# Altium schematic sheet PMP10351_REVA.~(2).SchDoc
size 431 x 279 mm; Date: Not shown in title block; ApprovedBy: Not shown in title block; CheckedBy: Not shown in title block; Author: Not shown in title block; CompanyName: Not shown in title block; Engineer: Not shown in title block; Organization: Not shown in title block; Address1: Not shown in title block; Address2: Not shown in title block; Address3: Not shown in title block; Address4: Not shown in title block; DocumentNumber: 1; Revision: Use project parameter SCH_Rev; SheetNumber: 1; SheetTotal: 1; PageSetup: Record=PageOptions|CenterHorizontal=True|CenterVertical=True|PrintScale=1.00|XCorrection=1.00|YCorrection=1.00|PrintKind=0|BorderSize=5000000|LeftOffset=0|BottomOffset=0|Orientation=2|PaperLength=1000|PaperWidth=1000|Scale=100|PaperSource=15|PrintQuality=600|MediaType=1|DitherType=10|PaperKind=Letter|PrintScaleMode=1
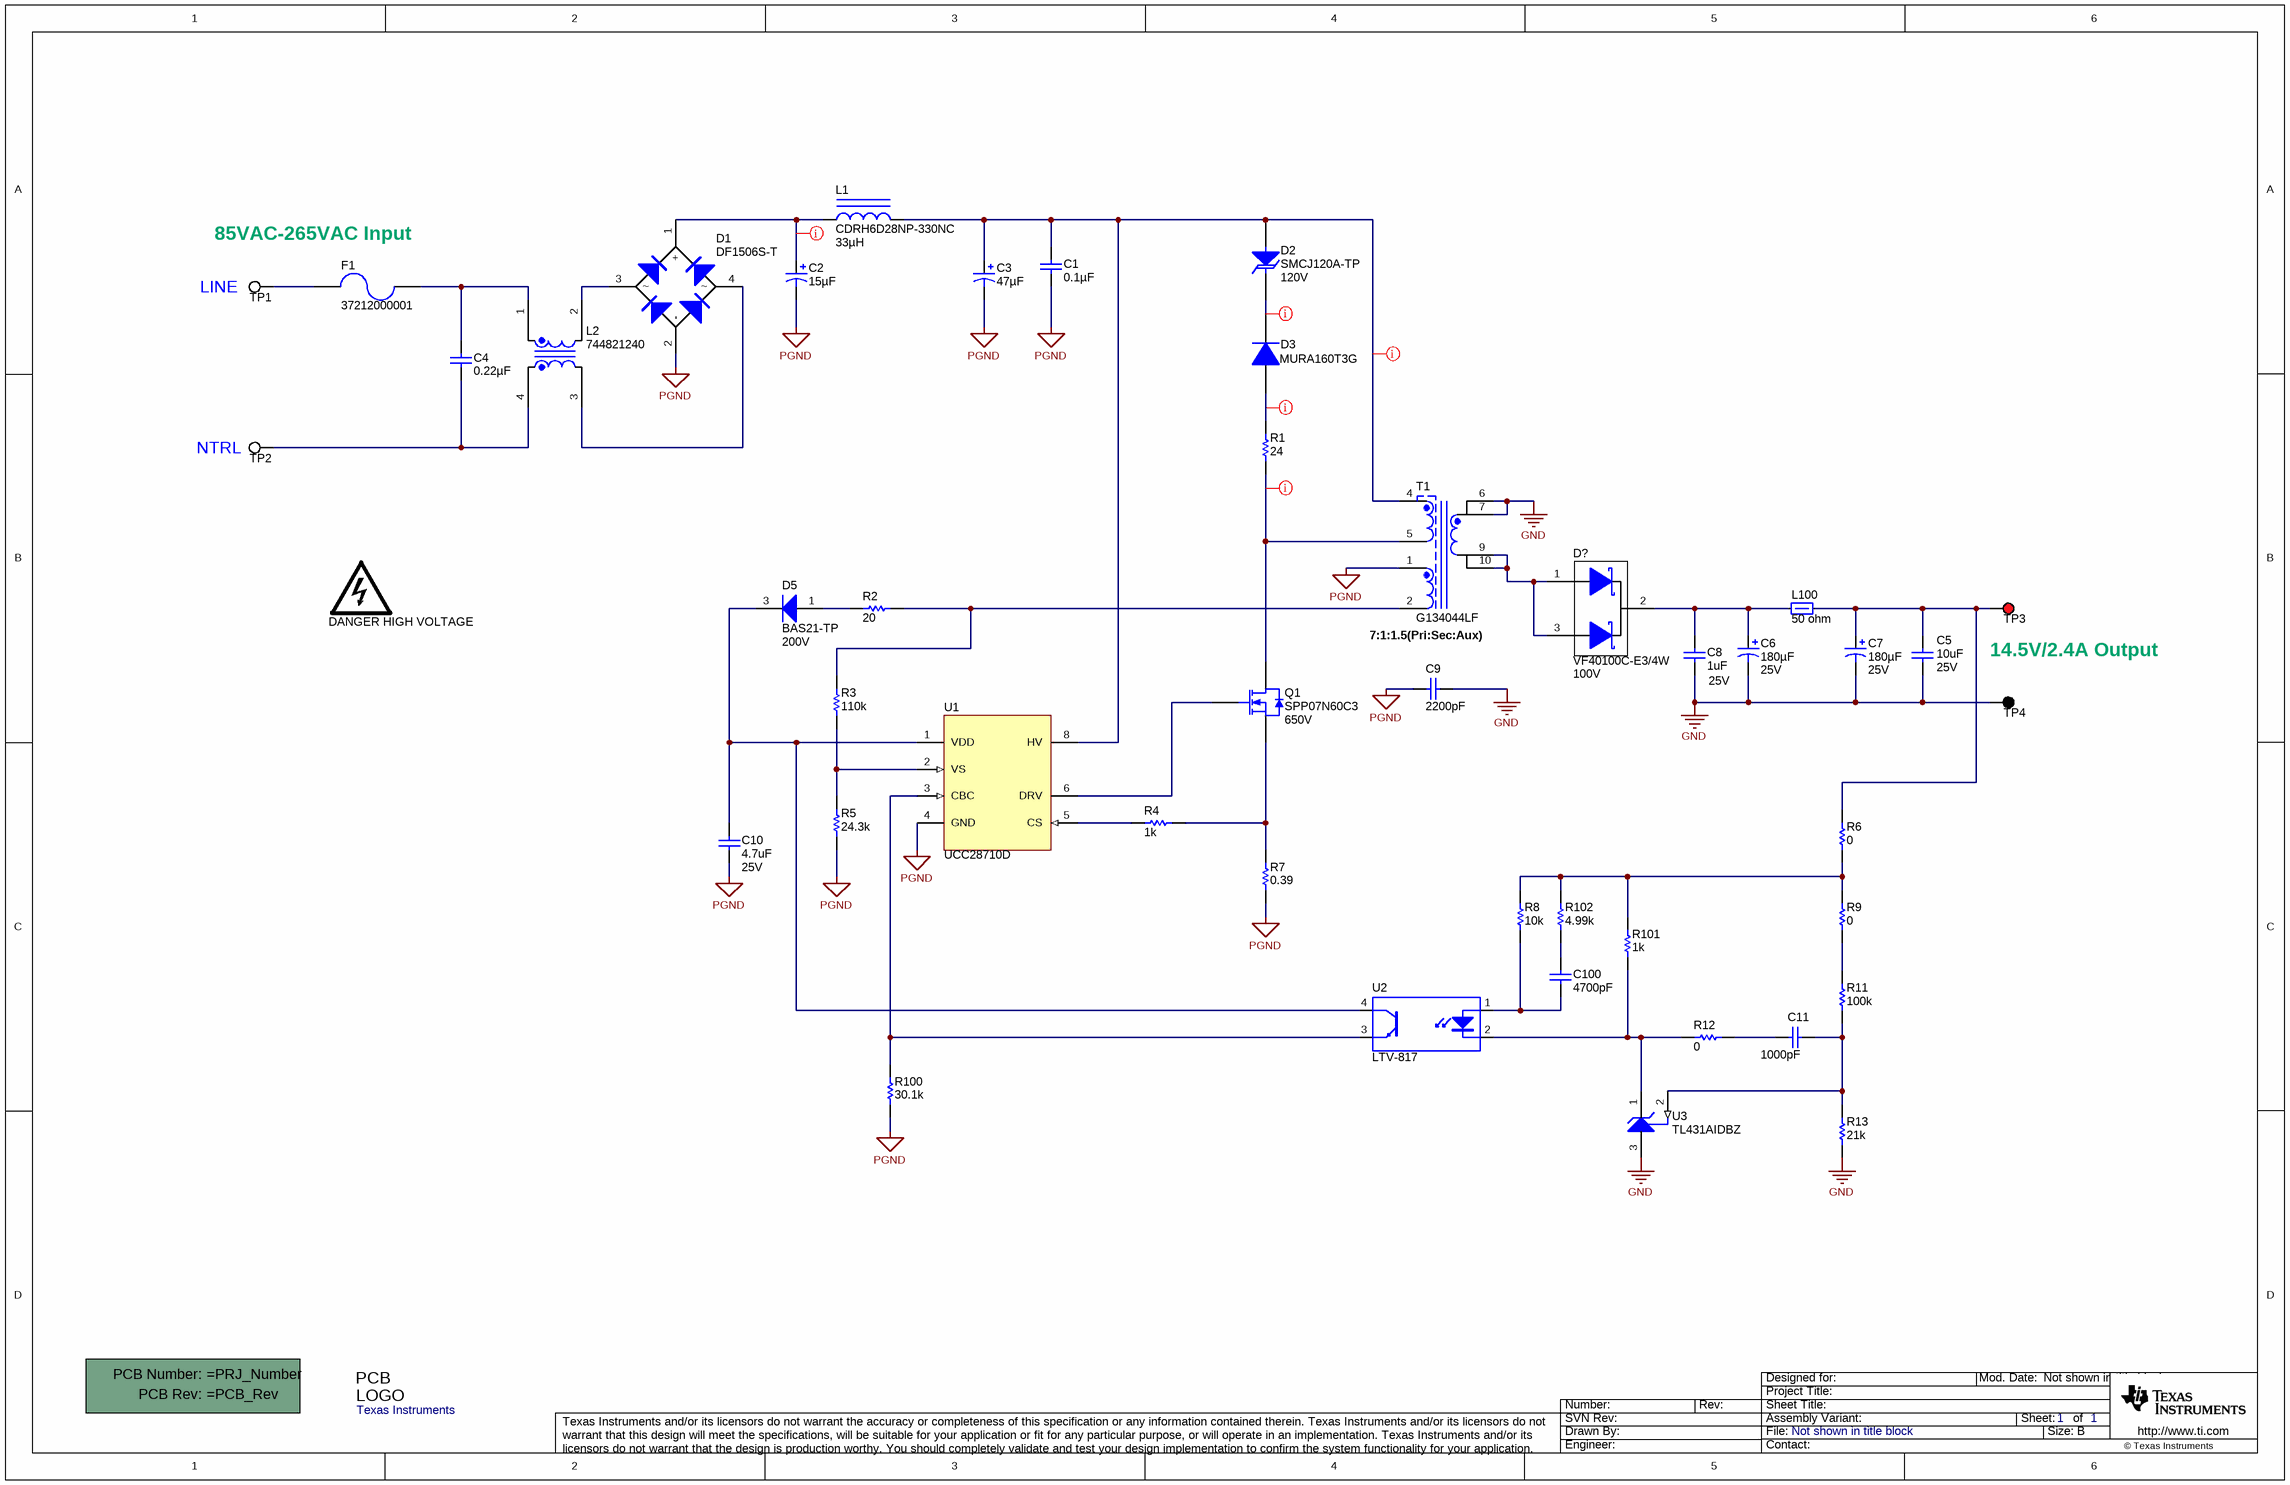
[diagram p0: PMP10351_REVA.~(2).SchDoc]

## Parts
(Parts that share a designator on the sheet are numbered #1, #2 ... from top to bottom, then left to right.)
!PCB  Printed Circuit Board  (value not drawn)  (mechanical)
C1  ValueDisplayed: 0.1µF  [1808_L]  (hidden comment: VJ1808Y104KXPAT5Z)
C2  ValueDisplayed: 15µF  [CAPPR5-12.5X20]  (hidden comment: EEUED2G150)
C3  ValueDisplayed: 47µF  [CAPPR7.5-18X20]  (hidden comment: EEUED2G470S)
C4  ValueDisplayed: 0.22µF  [B32922_12.5mm]  (hidden comment: B32922C3224M)
C5  value 10uF  Value2: 25V  [1206L]  (hidden comment: STD)
C6  ValueDisplayed: 180µF  Value2: 25V  [CAPPRD350W60D800H1150]  (hidden comment: 25SEPF180M)
C7  ValueDisplayed: 180µF  Value2: 25V  [CAPPRD350W60D800H1150]  (hidden comment: 25SEPF180M)
C8  value 1uF  Value2: 25V  [0805L]  (hidden comment: STD)
C9  ValueDisplayed: 2200pF  [CAPRD500W60D800H850]  (hidden comment: DE2E3KY222MA2BM01)
C10  value 4.7uF  Value2: 25V  [0805L]  (hidden comment: STD)
C11  value 1000pF  [0603L]  (hidden comment: STD)
C100  value 4700pF  [0603L]  (hidden comment: STD)
D1  DF1506S-T  [DF-S]
D2  SMCJ120A-TP  value 120V  [SMC]
D3  MURA160T3G  [SMA]
D5  BAS21-TP  value 200V  [SOT-23L]
D?  VF40100C-E3/4W  value 100V  [TO-220AB]
F1  37212000001  [FUSE_372]
L1  CDRH6D28NP-330NC  ValueDisplayed: 33µH  [CDRH6D28]
L2  744821240  [WE-CMB_XS]
L100  value 50 ohm  [1206L]  (hidden comment: HI1206T500R-10)
LOGO1#1  DANGER HIGH VOLTAGE  [IEC_HighVoltage_Small]  (no BOM)
Logo1#2  Texas Instruments  [TI_Stacked_SolderMask_Small]  (no BOM)
Q1  SPP07N60C3  value 650V  [TO-220AB]
R1  value 24  [2512L]  (hidden comment: STD)
R2  value 20  [0603L]  (hidden comment: STD)
R3  value 110k  [0603L]  (hidden comment: STD)
R4  value 1k  [0603L]  (hidden comment: STD)
R5  value 24.3k  [0603L]  (hidden comment: STD)
R6  value 0  [0603L]  (hidden comment: STD)
R7  value 0.39  [1210L]  (hidden comment: STD)
R8  value 10k  [0603L]  (hidden comment: STD)
R9  value 0  [0603L]  (hidden comment: STD)
R11  value 100k  [0603L]  (hidden comment: STD)
R12  value 0  [0603L]  (hidden comment: STD)
R13  value 21k  [0603L]  (hidden comment: STD)
R100  value 30.1k  [0603L]  (hidden comment: STD)
R101  value 1k  [0603L]  (hidden comment: STD)
R102  value 4.99k  [0603L]  (hidden comment: STD)
T1  G134044LF  [GCI_G134044LF]
TP1  5012  [Keystone5012]  (value not drawn)
TP2  5012  [Keystone5012]  (value not drawn)
TP3  5010  [Keystone5010]  (value not drawn)
TP4  5011  [Keystone5011]  (value not drawn)
U1  UCC28710D  [D0007A_L]
U2  LTV-817  [DIP762W60P254L460H350Q4B]
U3  TL431AIDBZ  [DBZ0003A_L]

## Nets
GND: C5.2 C6.2(-) C7.2(-) C8.2 C9.1 R13.1 T1.6 T1.7 TP4.1 U3.3(ANODE)
PGND: C1.2 C2.2(-) C3.2(-) C9.2 C10.2 D1.2(-) R5.1 R7.1 R100.1 T1.1 U1.4(GND)
NetC1_1: C1.1 C3.1(+) D2.2(A) L1.2 T1.4 U1.8(HV)
NetC2_1: C2.1(+) D1.1(+) L1.1
NetC4_1: C4.1 F1.1 L2.1
NetC4_2: C4.2 L2.4 TP2.1
NetC5_1: C5.1 C7.1(+) L100.2 R6.2 TP3.1
NetC6_1: C6.1(+) C8.1 D?.2(K) L100.1
NetC10_1: C10.1 D5.3(K) U1.1(VDD) U2.4(C)
NetC11_1: C11.1 R11.1 R13.2 U3.2(REF)
NetC11_2: C11.2 R12.1
NetC100_1: C100.1 R102.2
NetC100_2: C100.2 R8.1 U2.1(A)
NetD1_3: D1.3 L2.2
NetD1_4: D1.4 L2.3
NetD2_1: D2.1(K) D3.1(K)
NetD3_2: D3.2(A) R1.2
NetD5_1: D5.1(A) R2.2
NetD?_1: D?.1(A) D?.3(A) T1.9 T1.10
NetF1_2: F1.2 TP1.1
NetQ1_1: Q1.1(G) U1.6(DRV)
NetQ1_2: Q1.2(D) R1.1 T1.5
NetQ1_3: Q1.3(S) R4.1 R7.2
NetR2_1: R2.1 R3.2 T1.2
NetR3_1: R3.1 R5.2 U1.2(VS)
NetR4_2: R4.2 U1.5(CS)
NetR6_1: R6.1 R8.2 R9.2 R101.1 R102.1
NetR9_1: R9.1 R11.2
NetR12_2: R12.2 R101.2 U2.2(K) U3.1(CATHODE)
NetR100_2: R100.2 U1.3(CBC) U2.3(E)

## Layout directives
rule Clearance Constraint [Clearance = 24mil]: NetQ1_2
rule Clearance Constraint [Clearance = 25mil]: NetC1_1, NetC2_1, NetD2_1, NetD3_2

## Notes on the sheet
- 85VAC-265VAC Input
- (near TP1) LINE
- (near TP2) NTRL
- (near T1) 7:1:1.5(Pri:Sec:Aux)
- 14.5V/2.4A Output

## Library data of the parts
!PCB = PCB: Manufacturer: Any; SymbolCreator: a0412235
C1 = VJ1808Y104KXPAT5Z: CAP, CERM, 0.1uF, 250V, +/-10%, X7R, 1808; Manufacturer: Vishay-Vitramon; Polarized: N; CompType: Capacitor; U/M: EA; Cap_F: 0.0000001; Tolerance_%: 10; Value1: Unknown; VDC_V: 250; TaMin_C: -55; TaMax_C: 125; Cap_Case: 1808
C2 = EEUED2G150: CAP, AL, 15uF, 400V, +/-20%, 1.909859 ohm, TH; Manufacturer: Panasonic; Polarized: Y; CompType: Capacitor; U/M: EA; Cap_F: 0.000015; Tolerance_%: 20; VDC_V: 400; IRMS_A: 0.41; TaMin_C: -25; TaMax_C: 105; AC_Derating: 0.3
C3 = EEUED2G470S: CAP, AL, 47uF, 400V, +/-20%, 0.609529 ohm, TH; Manufacturer: Panasonic; Polarized: Y; CompType: Capacitor; U/M: EA; Cap_F: 0.000047; Tolerance_%: 20; VDC_V: 400; IRMS_A: 0.84; TaMin_C: -25; TaMax_C: 105; AC_Derating: 0.3
C4 = B32922C3224M: CAP, Film, 0.22uF, 630V, +/-20%, TH; Manufacturer: EPCOS Inc; Polarized: N; CompType: Capacitor; U/M: EA; Cap_F: 0.00000022; Tolerance_%: 20; Value1: Unknown; VDC_V: 630; TaMax_C: 110
C5 = C1206C103K5RACTU: CAP, CERM, 25V, +/-10%, X5R, 1206; Polarized: N; CompType: Capacitor; ValueDisplayed: 0.01µF; U/M: EA; Cap_F: 0.00000001; Tolerance_%: 10; ESR_Ohm: 0.155; Value1: 0.155 ohm; VDC_V: 50; TempCo: X7R; IRMS_A: 0.416; TaMin_C: -55; TaMax_C: 125; Cap_Case: 1206
C6 C7 = 200LLE10MEFC8X11.5: CAP ALUM 180UF 25V 20% RADIAL; Manufacturer: Panasonic; Polarized: Y; CompType: Capacitor; U/M: EA; Cap_F: 0.00001; Tolerance_%: 20; Value1: Unknown; VDC_V: 200; IRMS_A: 0.08; TaMin_C: -40; TaMax_C: 105; Cap_Case: Radial 8x11.5mm
C8 C10 = GQM2195C2A2R0CB01D: CAP, CERM, 25V, +/-10%, X7R, 0805; Polarized: N; CompType: Capacitor; ValueDisplayed: 2pF; U/M: EA; Cap_F: 0.000000000002; Tolerance_%: 5; Value1: Unknown; VDC_V: 100; TempCo: C0G/NP0; TaMin_C: -55; TaMax_C: 125; Cap_Case: 0805
C9 = DE2E3KY222MA2BM01: CAP, CERM, 2200pF, 250V, +/-20%, KY, Radial D8x5mm; Manufacturer: MuRata; Polarized: N; CompType: Capacitor; U/M: EA; Cap_F: 0.0000000022; Tolerance_%: 20; Value1: Unknown; VDC_V: 250; TaMin_C: -25; TaMax_C: 85
C11 C100 = 06031C221KAT2A: CAP, CERM, 50V, +/-10%, X7R, 0603; Polarized: N; CompType: Capacitor; ValueDisplayed: 220pF; U/M: EA; Cap_F: 0.00000000022; Tolerance_%: 10; ESR_Ohm: 0.579; Value1: 0.579 ohm; VDC_V: 100; Value2: 100V; TaMin_C: -55; TaMax_C: 125; Cap_Case: 0603
D1 = DF1506S-T: Diode, Switching-Bridge, 600V, 1.5A, DF-S; Manufacturer: Diodes Inc.; Value: 1.1V; U/M: EA; Vf_V: 1.1; Io_A: 1.5; Vr_V: 600; TJmax_C: 150
D2 = SMCJ120A-TP: Diode, TVS, Uni, 120V, 1500W, SMC; Manufacturer: Micro Commercial Components; U/M: EA; Power_W: 1500; Vr_V: 120
D3 = MURA160T3G: Diode, Ultrafast, 600V, 1A, SMA; Manufacturer: ON Semiconductor; Value: 1.05V; U/M: EA; Vf_V: 1.05; Io_A: 1; Vr_V: 600; TJmax_C: 175
D5 = BAS21-TP: Diode, P-N, 200V, 200A, SOT-23; Manufacturer: Micro Commercial Components; U/M: EA; Vf_V: 1.25; Io_A: 200; Value2: 1.25V; TJmax_C: 150; RJC_CperW: 430
D? = VF40100C-E3/4W: Diode, Schottky, 100V, 20A, TH; Manufacturer: Vishay-Semiconductor; SymbolCreator: a0411947; U/M: EA; Vf_V: 0.73; Value2: 0.73V; Io_A: 20; Vr_V: 100; TJmax_C: 150; RJC_CperW: 2
F1 = 37215000001: Fuse, 2A, 250V, TH; Manufacturer: Littelfuse; U/M: EA; OpeningTime_100%_min: 4; OpeningTime_200%_max: 2; VDC_V: 250; Irating_A: 5; MeltingTyp: 94; Vdrop: 0.08; Soldering_Wave_MaxTemp_C: 260
L1 = CDRH6D28NP-330NC: Inductor, Shielded Drum Core, Ferrite, 33uH, 0.97A, 0.165 ohm, SMD; Manufacturer: Sumida; Ind_H: 33.0E-6; Imax_A: 0.97; Irms: 0.97A @ 30C rise; Isat: 0.97A @ 35% inductance drop; DCR_ohm: 0.165; U/M: EA
L2 = 744821240: Coupled inductor, 4000uH, 1.5A, 0.14 ohm, +/-30%, TH; Manufacturer: Wurth Elektronik eiSos; SymbolCreator: a0412235; Ind_H: 0.004; DCR_Ohm: 0.14; Isat: 1.5; Tolerance_%: 30; U/M: EA
L100 = HI1206T500R-10: 6A Ferrite Bead, 50 ohm @ 100MHz, SMD; Manufacturer: Steward; Imax_A: 6; DCR_ohm: 0.01; Value1: 0.01 ohm; ZTyp@100MHz_Ohm: 50; Ztyp@1GHz_Ohm: 70; U/M: EA
LOGO1#1 = IEC_HighVoltage: IEC 61010-1 High Voltage Warning; SymbolCreator: a0412235
Logo1#2 = TI_Logo: Texas Instrument Corporate Signature; SymbolCreator: a0412235
Q1 = SPP07N60C3: MOSFET, N-CH, 650V, 7.3A, TO-220AB; Manufacturer: Infineon Technologies; Alternate Manufacturer: None; U/M: EA; ChType: N; VdsMax_V: 650; Value1: ? ohm; Value2: 21 nC; QgTyp_nC: 21; Vgs_V: 20; IdsMax_A: 7.3
R1 = 73M1R007F: RES, 1%, 1W, 2512; CompType: Resistor; Res_ohm: 0.007; Value_Code: R007; Tolerance_%: 1; TempCo: 180 ppm/C; EIA_Code: E96; U/M: EA
R2-R5 R8 R11 R13 R100-R102 = CRCW06030000Z0EA: RES,  1%, 0.1W, 0603; CompType: Resistor; Res_ohm: 0; Value_Code: 0000; Tolerance_%: 5; Value1: 5%; Power_W: 0.1; VDC_V: 75; TempCo: 200 ppm/C; EIA_Code: E24; U/M: EA
R6 R9 R12 = CRCW06030000Z0EA: RES,  1%, 0.1W, 0603; CompType: Resistor; Value_Code: 0000; Tolerance_%: 5; Value1: 5%; Power_W: 0.1; VDC_V: 75; TempCo: 200 ppm/C; EIA_Code: E24; U/M: EA
R7 = ERJ-L14KF10CU: RES, 1%, 0.33W, 1210; CompType: Resistor; Res_ohm: 0.1; Value_Code: R100; Tolerance_%: 1; Power_W: 0.33; TempCo: 100 ppm/C; EIA_Code: E96; U/M: EA
T1 = G134044LF: Transformer, 300uH, TH; Manufacturer: GCI Technologies; SymbolCreator: a0411947; DCR_Ohm: 1.25; LeakageL: 4.5uH; U/M: EA
TP1 TP2 = 5012: Test Point, Multipurpose, White, TH; Manufacturer: Keystone; CompType: Test Point Loop; U/M: EA
TP3 = 5010: Test Point, Multipurpose, Red, TH; Manufacturer: Keystone; CompType: Test Point Loop; U/M: EA
TP4 = 5011: Test Point, Multipurpose, Black, TH; Manufacturer: Keystone; CompType: Test Point Loop; U/M: EA
U1 = UCC28710D: Constant-Voltage, Constant-Current Controller With Primary-Side Regulation, D0007A; Alternate Manufacturer: None; Manufacturer: Texas Instruments; SymbolCreator: a0411947; CompType: IC; U/M: EA
U2 = LTV-817: Opto-Isolator, 1 Channel, TH; Manufacturer: Lite-On; CompType: OPTOCOUPLER; U/M: EA
U3 = TL431AIDBZ: PRECISION PROGRAMMABLE REFERENCE, DBZ0003A; Alternate Manufacturer: None; Manufacturer: Texas Instruments; SymbolCreator: a0412235; CompType: IC; U/M: EA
